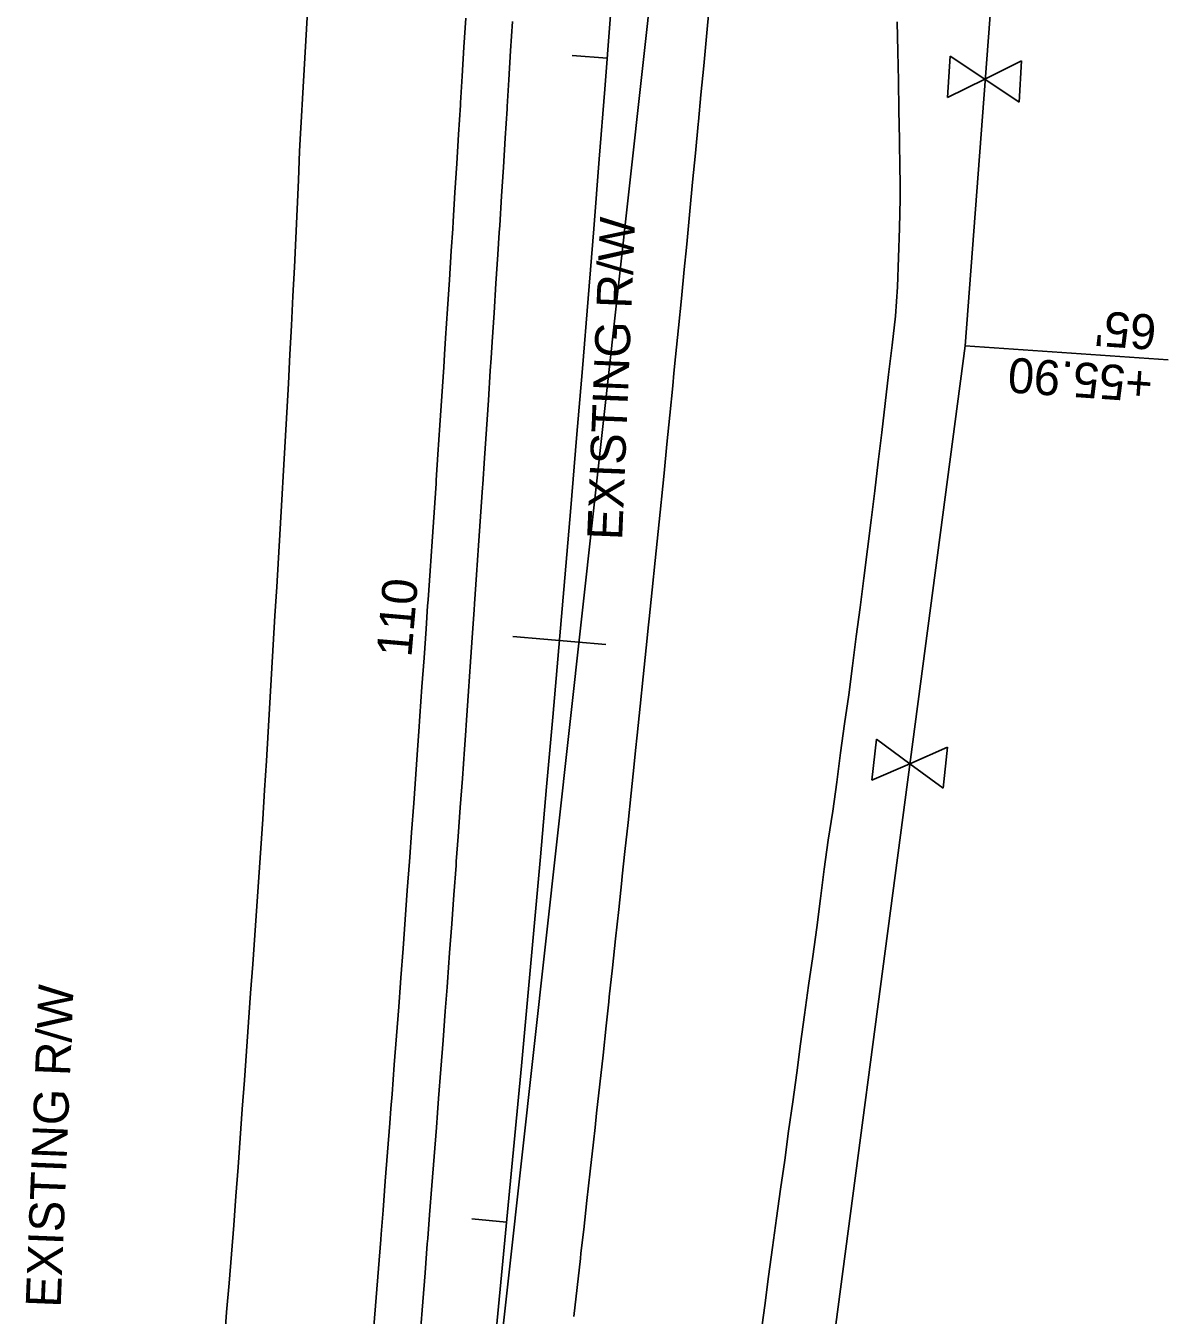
# Model space of a CAD drawing. Extents: x 634057 to 641016, y 287858 to 292331.
# Drawn here: x 634192.3 to 634387.8, y 289750.2 to 289971 of the extents above; entities that cross this region are included whole.
import ezdxf

# ---------------------------------------------------------------- set-up
doc = ezdxf.new("R2010")
doc.units = 0
for name, color, linetype in [('53', 7, 'Continuous'), ('R_50 Horz Alg PC PI PT', 7, 'Continuous'), ('R_50 Horz Alg Stations', 7, 'Continuous'), ('R_50 Horz Alg Ticks', 7, 'Continuous'), ('R_Horz Alg', 7, 'Continuous'), ('R_No Plot', 7, 'Continuous'), ('R_Proposed Const Limits', 7, 'Continuous'), ('R_Proposed Road', 7, 'Continuous'), ('R_Proposed Shoulder', 7, 'Continuous'), ('R_ROW', 7, 'Continuous')]:
    doc.layers.add(name, color=color, linetype=linetype)

msp = doc.modelspace()

# ---------------------------------------------------------------- linework, layer by layer
at = {"layer": '53'}
msp.add_line((634353.08, 289916.2), (634387.84, 289913.78), dxfattribs=at)
at = {"layer": 'R_50 Horz Alg PC PI PT'}
msp.add_lwpolyline([(634256.46, 289590.15), (634341.05, 290353.77)], dxfattribs=at)
at = {"layer": 'R_50 Horz Alg Ticks'}
for points in [[(634285.81, 289965.9), (634291.79, 289965.44)], [(634275.65, 289866.46), (634291.59, 289865.08)], [(634268.61, 289766.75), (634274.58, 289766.18)]]:
    msp.add_lwpolyline(points, dxfattribs=at)
at = {"layer": 'R_Horz Alg'}
msp.add_arc((622866.97, 290851.82), 11459.16, 353.678846, 1.350269, dxfattribs=at)
at = {"layer": 'R_Proposed Const Limits'}
for points in [[(634226.26, 289745.77), (634226.65, 289750.74), (634227.07, 289755.7), (634227.5, 289760.66), (634227.88, 289765.63), (634228.24, 289770.59), (634228.6, 289775.56), (634228.96, 289780.53), (634229.32, 289785.5), (634229.68, 289790.46), (634230.04, 289795.43), (634230.4, 289800.4), (634230.75, 289805.37), (634231.11, 289810.33), (634231.46, 289815.3), (634231.82, 289820.27), (634232.17, 289825.24), (634232.5, 289830.21), (634232.82, 289835.18), (634233.14, 289840.15), (634233.45, 289845.12), (634233.76, 289850.09), (634234.06, 289855.06), (634234.35, 289860.03), (634234.63, 289865.01), (634234.92, 289869.98), (634235.23, 289874.95), (634235.53, 289879.92), (634235.82, 289884.89), (634236.11, 289889.86), (634236.39, 289894.84), (634236.68, 289899.81), (634236.96, 289904.78), (634237.23, 289909.75), (634237.49, 289914.73), (634237.75, 289919.7), (634238, 289924.68), (634238.25, 289929.65), (634238.48, 289934.62), (634238.71, 289939.6), (634238.94, 289944.58), (634239.15, 289949.55), (634239.31, 289952.58), (634239.43, 289954.52), (634239.72, 289959.49), (634240, 289964.46), (634240.28, 289969.43), (634240.55, 289974.41)], [(634341.43, 289971.66), (634341.54, 289966.62), (634341.65, 289961.57), (634341.74, 289956.53), (634341.83, 289951.48), (634341.91, 289946.44), (634341.94, 289944.46), (634341.96, 289941.4), (634341.83, 289936.37), (634341.68, 289931.34), (634341.52, 289926.31), (634341.15, 289921.3), (634340.56, 289916.31), (634339.97, 289911.32), (634339.41, 289906.33), (634338.8, 289901.34), (634338.19, 289896.35), (634337.59, 289891.36), (634337, 289886.37), (634336.37, 289881.38), (634335.73, 289876.4), (634335.09, 289871.41), (634334.44, 289866.43), (634333.82, 289861.44), (634333.16, 289856.45), (634332.44, 289851.48), (634331.73, 289846.5), (634331.1, 289841.51), (634330.4, 289836.53), (634329.65, 289831.56), (634328.96, 289826.58), (634328.34, 289821.59), (634327.69, 289816.61), (634326.98, 289811.63), (634326.26, 289806.66), (634325.56, 289801.68), (634324.91, 289796.7), (634324.26, 289791.71), (634323.55, 289786.74), (634322.85, 289781.76), (634322.19, 289776.78), (634321.48, 289771.81), (634320.77, 289766.83), (634320.1, 289761.85), (634319.44, 289756.87), (634318.77, 289751.89), (634318.1, 289746.91)]]:
    msp.add_lwpolyline(points, dxfattribs=at)
at = {"layer": 'R_Proposed Road'}
for points in [[(634286.09, 289750), (634286.65, 289754.98), (634287.21, 289759.95), (634287.31, 289760.86), (634287.77, 289764.93), (634288.33, 289769.9), (634288.88, 289774.88), (634289.43, 289779.86), (634289.71, 289782.37), (634289.98, 289784.83), (634290.53, 289789.81), (634291.08, 289794.78), (634291.62, 289799.76), (634292.07, 289803.88), (634292.16, 289804.74), (634292.7, 289809.72), (634293.23, 289814.7), (634293.77, 289819.67), (634294.3, 289824.65), (634294.38, 289825.39), (634294.83, 289829.63), (634295.36, 289834.61), (634295.89, 289839.59), (634296.41, 289844.57), (634296.65, 289846.91), (634296.93, 289849.55), (634297.45, 289854.53), (634297.97, 289859.51), (634298.48, 289864.49), (634298.89, 289868.44), (634298.99, 289869.47), (634299.5, 289874.45), (634300.01, 289879.43), (634300.52, 289884.41), (634301.02, 289889.4), (634301.08, 289889.97), (634301.53, 289894.38), (634302.03, 289899.36), (634302.52, 289904.34), (634303.02, 289909.33), (634303.23, 289911.5), (634303.51, 289914.31), (634304, 289919.29), (634304.49, 289924.28), (634304.98, 289929.26), (634305.35, 289933.04), (634305.46, 289934.25), (634305.94, 289939.23), (634306.42, 289944.21), (634306.9, 289949.2), (634307.38, 289954.18), (634307.42, 289954.58), (634307.85, 289959.17), (634308.32, 289964.16), (634308.79, 289969.14), (634309.26, 289974.13)], [(634259.81, 289747.52), (634260.21, 289752.5), (634260.61, 289757.48), (634261, 289762.46), (634261.07, 289763.37), (634261.39, 289767.44), (634261.78, 289772.42), (634262.17, 289777.4), (634262.55, 289782.38), (634262.74, 289784.89), (634262.93, 289787.36), (634263.31, 289792.34), (634263.69, 289797.32), (634264.07, 289802.3), (634264.38, 289806.42), (634264.44, 289807.28), (634264.81, 289812.26), (634265.18, 289817.24), (634265.55, 289822.22), (634265.92, 289827.2), (634265.97, 289827.94), (634266.28, 289832.18), (634266.64, 289837.17), (634267, 289842.15), (634267.35, 289847.13), (634267.52, 289849.47), (634267.71, 289852.11), (634268.06, 289857.09), (634268.41, 289862.07), (634268.76, 289867.06), (634269.03, 289871), (634269.1, 289872.04), (634269.45, 289877.02), (634269.79, 289882), (634270.13, 289886.99), (634270.46, 289891.97), (634270.5, 289892.54), (634270.8, 289896.95), (634271.13, 289901.93), (634271.46, 289906.92), (634271.79, 289911.9), (634271.93, 289914.07), (634272.12, 289916.88), (634272.44, 289921.87), (634272.76, 289926.85), (634273.08, 289931.83), (634273.32, 289935.61), (634273.4, 289936.82), (634273.71, 289941.8), (634274.03, 289946.79), (634274.34, 289951.77), (634274.65, 289956.75), (634274.67, 289957.15), (634274.95, 289961.74), (634275.26, 289966.72), (634275.56, 289971.71)]]:
    msp.add_lwpolyline(points, dxfattribs=at)
at = {"layer": 'R_Proposed Shoulder'}
msp.add_lwpolyline([(634251.85, 289748.29), (634252.25, 289753.27), (634252.64, 289758.24), (634253.04, 289763.22), (634253.11, 289764.13), (634253.43, 289768.2), (634253.81, 289773.17), (634254.2, 289778.15), (634254.59, 289783.13), (634254.78, 289785.64), (634254.97, 289788.1), (634255.35, 289793.08), (634255.73, 289798.06), (634256.1, 289803.03), (634256.41, 289807.15), (634256.48, 289808.01), (634256.85, 289812.99), (634257.22, 289817.96), (634257.58, 289822.94), (634257.95, 289827.92), (634258, 289828.66), (634258.31, 289832.9), (634258.67, 289837.88), (634259.03, 289842.85), (634259.39, 289847.83), (634259.55, 289850.17), (634259.74, 289852.81), (634260.09, 289857.79), (634260.44, 289862.77), (634260.79, 289867.75), (634261.06, 289871.69), (634261.13, 289872.72), (634261.48, 289877.7), (634261.82, 289882.68), (634262.16, 289887.66), (634262.49, 289892.64), (634262.53, 289893.21), (634262.83, 289897.62), (634263.16, 289902.6), (634263.49, 289907.58), (634263.82, 289912.56), (634263.96, 289914.73), (634264.14, 289917.54), (634264.47, 289922.52), (634264.79, 289927.5), (634265.11, 289932.48), (634265.35, 289936.25), (634265.42, 289937.46), (634265.74, 289942.44), (634266.05, 289947.42), (634266.36, 289952.4), (634266.67, 289957.38), (634266.69, 289957.78), (634266.98, 289962.36), (634267.28, 289967.34), (634267.58, 289972.32)], dxfattribs=at)
at = {"layer": 'R_ROW'}
for p, q in [((634350.08, 289958.72), (634350.54, 289965.78)), ((634350.54, 289965.78), (634356.42, 289961.85)), ((634356.42, 289961.85), (634362.75, 289964.99)), ((634362.75, 289964.99), (634362.3, 289957.93)), ((634356.42, 289961.85), (634350.08, 289958.72)), ((634362.3, 289957.93), (634356.42, 289961.85)), ((634337.12, 289841.83), (634337.92, 289848.85)), ((634337.92, 289848.85), (634343.6, 289844.65)), ((634343.6, 289844.65), (634350.08, 289847.48)), ((634350.08, 289847.48), (634349.29, 289840.45)), ((634343.6, 289844.65), (634337.12, 289841.83)), ((634349.29, 289840.45), (634343.6, 289844.65))]:
    msp.add_line(p, q, dxfattribs=at)
msp.add_lwpolyline([(634329.31, 289374.55), (634319.38, 289660.99), (634353.08, 289916.2), (634363.24, 290050.68)], dxfattribs=at)

# ---------------------------------------------------------------- texts
at = {"layer": '53'}
for s, rotation, p in [('EXISTING R/W', 87.6932, (634294.35, 289882.87)), ("65'  ", 176.0137, (634385.99, 289921.47)), ('+55.90 ', 176.0137, (634385.36, 289912.5)), ('EXISTING R/W', 87.6932, (634198.23, 289751.47))]:
    msp.add_text(s, height=6, rotation=rotation, dxfattribs=at).set_placement(p)
at = {"layer": 'R_50 Horz Alg Stations'}
msp.add_text('110', height=6, rotation=85.0637, dxfattribs=at).set_placement((634258.27, 289862.77))
at = {"layer": 'R_No Plot'}
msp.add_text('+', height=0.1, rotation=84.9914, dxfattribs=at).set_placement((634282.41, 289851.32))

doc.saveas('drawing.dxf')
